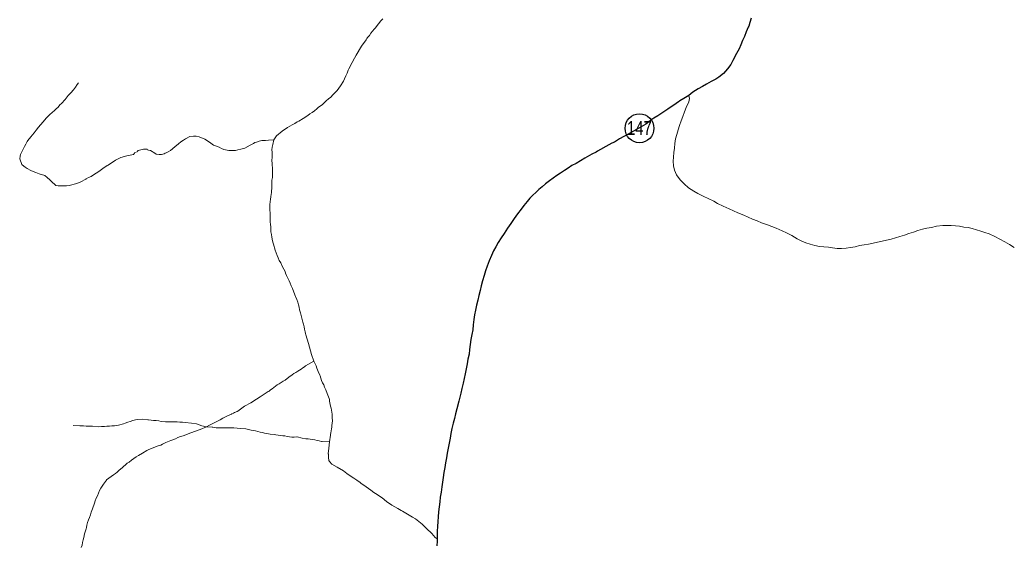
# Model space of a CAD drawing. Extents: x 781.9 to 808.1, y 7453.3 to 7481.5.
# Drawn here: x 790.69 to 796.4, y 7473.15 to 7476.16 of the extents above; entities that cross this region are included whole.
import ezdxf
from ezdxf.enums import TextEntityAlignment as Align

# ---------------------------------------------------------------- set-up
doc = ezdxf.new("R2010")
doc.units = 0
doc.header["$LTSCALE"] = 0.032
doc.linetypes.add('LONG_DASHED', pattern=[7.5, 6, -1.5])
doc.linetypes.add('MEDIUM_DASHED', pattern=[4.5, 3, -1.5])
for name, color, linetype, lineweight in [('13', 7, 'Continuous', 25), ('4', 7, 'LONG_DASHED', 25), ('5', 7, 'LONG_DASHED', 13), ('6', 7, 'MEDIUM_DASHED', 13)]:
    doc.layers.add(name, color=color, linetype=linetype, lineweight=lineweight)
doc.layers.add('61', color=7, linetype='Continuous')

msp = doc.modelspace()

# ---------------------------------------------------------------- linework, layer by layer
at = {"layer": '13'}
msp.add_circle((794.2522, 7475.5387), 0.083, dxfattribs=at)
msp.add_circle((794.2522, 7475.5387), 0.083, dxfattribs=at)
msp.add_circle((794.2522, 7475.5387), 0.083, dxfattribs=at)
at = {"layer": '4'}
for points in [[(794.8957, 7476.1726), (794.8876, 7476.1483), (794.8819, 7476.1264), (794.8778, 7476.1207), (794.8666, 7476.0932), (794.8568, 7476.0672), (794.8454, 7476.0429), (794.8349, 7476.0186), (794.826, 7475.9967), (794.8114, 7475.9691), (794.7902, 7475.9294), (794.7773, 7475.9051), (794.7586, 7475.8799), (794.7351, 7475.854), (794.7084, 7475.8329), (794.6906, 7475.8215), (794.6646, 7475.8069), (794.6387, 7475.7931), (794.6144, 7475.7786), (794.59, 7475.7656), (794.5588, 7475.7456), (794.5364, 7475.7272)], [(794.5364, 7475.7272), (794.5076, 7475.7104), (794.4852, 7475.696), (794.483, 7475.6942), (794.4765, 7475.6902), (794.4635, 7475.6805), (794.4149, 7475.648), (794.3582, 7475.6107), (794.3338, 7475.5961), (794.3233, 7475.5897), (794.2889, 7475.5625), (794.2481, 7475.5385), (794.1873, 7475.5057), (794.1377, 7475.4777), (794.1073, 7475.4585), (794.0922, 7475.4526), (794.076, 7475.4437), (794.0111, 7475.4064), (794.0022, 7475.4016), (793.9787, 7475.3902), (793.9382, 7475.3659), (793.9122, 7475.3504), (793.8879, 7475.3367), (793.8636, 7475.3237), (793.8417, 7475.3091), (793.8198, 7475.2953), (793.7979, 7475.2807), (793.7768, 7475.2669), (793.7549, 7475.2516), (793.7338, 7475.2353), (793.7119, 7475.2183), (793.6917, 7475.2021), (793.6722, 7475.1867), (793.656, 7475.1697), (793.6374, 7475.1542), (793.6203, 7475.1364), (793.6049, 7475.1178), (793.5863, 7475.0943), (793.5701, 7475.0732), (793.5506, 7475.0456), (793.5312, 7475.0197), (793.5117, 7474.9905), (793.4914, 7474.9629), (793.4728, 7474.9338), (793.4557, 7474.9078), (793.4395, 7474.8819), (793.4251, 7474.8563), (793.4123, 7474.8339), (793.4003, 7474.8059), (793.3868, 7474.7749), (793.3755, 7474.7457), (793.3666, 7474.7181), (793.3585, 7474.6905), (793.3479, 7474.6613), (793.3406, 7474.6322), (793.3342, 7474.6046), (793.3277, 7474.577)], [(793.3277, 7474.577), (793.3212, 7474.5495), (793.3139, 7474.5203), (793.3074, 7474.4927), (793.3025, 7474.4652), (793.2993, 7474.4376), (793.2944, 7474.4084)], [(793.2944, 7474.4084), (793.292, 7474.3792), (793.2871, 7474.3516), (793.2822, 7474.3241), (793.2774, 7474.2949), (793.2741, 7474.2657), (793.2709, 7474.2381), (793.2644, 7474.2106), (793.2595, 7474.183), (793.2539, 7474.1538), (793.249, 7474.1262), (793.2433, 7474.0987), (793.2368, 7474.0711), (793.2295, 7474.0419), (793.2231, 7474.0144), (793.2198, 7473.9989), (793.2125, 7473.969), (793.2012, 7473.9236), (793.1931, 7473.896), (793.1866, 7473.8684), (793.1801, 7473.8409), (793.1728, 7473.8117), (793.1663, 7473.7825), (793.1614, 7473.7549), (793.1566, 7473.7273), (793.1501, 7473.6982), (793.1444, 7473.669), (793.1404, 7473.6414), (793.1355, 7473.6138), (793.1314, 7473.5863), (793.1266, 7473.5571), (793.1217, 7473.5295), (793.1185, 7473.502), (793.1136, 7473.4744), (793.1096, 7473.4452), (793.1047, 7473.416), (793.1023, 7473.3884), (793.099, 7473.3609), (793.0958, 7473.3317), (793.0933, 7473.3025), (793.0909, 7473.2749), (793.0893, 7473.2474), (793.0877, 7473.2198), (793.0878, 7473.1767)], [(793.0878, 7473.1767), (793.0877, 7473.1631), (793.0861, 7473.1355)]]:
    msp.add_lwpolyline(points, dxfattribs=at)
at = {"layer": '5'}
msp.add_lwpolyline([(794.5364, 7475.7272), (794.5404, 7475.7106), (794.5364, 7475.6906), (794.5203, 7475.6586), (794.5106, 7475.6326), (794.5008, 7475.6067), (794.4927, 7475.5808), (794.4822, 7475.5548), (794.4741, 7475.5289), (794.4668, 7475.5029), (794.4603, 7475.477), (794.4562, 7475.451), (794.453, 7475.4251), (794.4505, 7475.3991), (794.4473, 7475.3732), (794.4465, 7475.3489), (794.4481, 7475.3229), (794.4538, 7475.297), (794.4643, 7475.271), (794.487, 7475.2427), (794.5089, 7475.2183), (794.5341, 7475.1956), (794.5649, 7475.177), (794.5884, 7475.164), (794.6224, 7475.1462), (794.6468, 7475.134), (794.6792, 7475.1194), (794.7019, 7475.1064), (794.7343, 7475.091), (794.7676, 7475.0748), (794.7927, 7475.0635), (794.8187, 7475.0529), (794.8519, 7475.0383), (794.877, 7475.0262), (794.903, 7475.0156), (794.9289, 7475.0059), (794.9549, 7474.9954), (794.9889, 7474.9824), (795.0132, 7474.9727), (795.0392, 7474.9637), (795.0732, 7474.9491), (795.0976, 7474.9378), (795.1291, 7474.9208), (795.1592, 7474.9021), (795.1835, 7474.89), (795.2095, 7474.8802), (795.2354, 7474.8721), (795.2613, 7474.8648), (795.2873, 7474.8583), (795.3132, 7474.8567), (795.3392, 7474.8543), (795.3635, 7474.8502), (795.3894, 7474.847), (795.4154, 7474.8462), (795.4413, 7474.8478), (795.4673, 7474.8527), (795.4932, 7474.8567), (795.5192, 7474.8632), (795.5451, 7474.8681), (795.5711, 7474.8713), (795.597, 7474.8778), (795.6229, 7474.8835), (795.6489, 7474.8892), (795.6748, 7474.8956), (795.7008, 7474.9013), (795.7251, 7474.9078), (795.751, 7474.9151), (795.777, 7474.9232), (795.8029, 7474.9329), (795.8289, 7474.9402), (795.8548, 7474.9499), (795.8808, 7474.9589), (795.9067, 7474.9629), (795.9327, 7474.9686), (795.9615, 7474.976), (795.9983, 7474.9792), (796.0218, 7474.9792), (796.0462, 7474.9783), (796.0705, 7474.9775), (796.0948, 7474.9751), (796.1191, 7474.9702), (796.1435, 7474.967), (796.1678, 7474.9613), (796.1921, 7474.9548), (796.2164, 7474.9475), (796.2407, 7474.9394), (796.2651, 7474.9313), (796.2967, 7474.9167), (796.3258, 7474.9005), (796.3551, 7474.8851), (796.3826, 7474.8689), (796.4093, 7474.8519)], dxfattribs=at)
at = {"layer": '6'}
for points in [[(792.7739, 7476.1693), (792.7625, 7476.1564), (792.7504, 7476.1402), (792.7301, 7476.115), (792.7244, 7476.1085), (792.7155, 7476.0972), (792.7066, 7476.0858), (792.6977, 7476.0721), (792.6871, 7476.0607), (792.6855, 7476.0591), (792.6839, 7476.055), (792.6806, 7476.0534), (792.6793, 7476.0476), (792.6524, 7476.0111), (792.6215, 7475.9586), (792.6125, 7475.9424), (792.5979, 7475.918), (792.5793, 7475.8815), (792.5761, 7475.8726), (792.5687, 7475.8564), (792.5615, 7475.8402), (792.5534, 7475.824), (792.5485, 7475.8094), (792.5307, 7475.7834), (792.512, 7475.7567), (792.5015, 7475.746), (792.4861, 7475.7307), (792.4747, 7475.7185), (792.4626, 7475.708), (792.4488, 7475.6966), (792.4269, 7475.6764), (792.4034, 7475.6578), (792.3945, 7475.6504), (792.3815, 7475.6399), (792.3685, 7475.6302), (792.3555, 7475.6212), (792.3426, 7475.6131), (792.3166, 7475.5953), (792.2915, 7475.5799), (792.2826, 7475.5751), (792.268, 7475.5661), (792.2534, 7475.558), (792.2396, 7475.5507), (792.2258, 7475.5426), (792.1949, 7475.5219)], [(790.6967, 7475.404), (790.7048, 7475.4186), (790.7129, 7475.4332), (790.7194, 7475.4478), (790.7283, 7475.4624), (790.7308, 7475.468), (790.7494, 7475.4899), (790.7673, 7475.5118), (790.7802, 7475.528), (790.7924, 7475.5451), (790.8045, 7475.5589), (790.8192, 7475.5751), (790.8378, 7475.5969), (790.8564, 7475.6164), (790.8726, 7475.631), (790.8832, 7475.6399), (790.8953, 7475.6496), (790.9059, 7475.661), (790.9164, 7475.6732), (790.9246, 7475.6821), (790.9456, 7475.7048), (790.9634, 7475.7267), (790.9788, 7475.742), (790.9943, 7475.7591), (791.0064, 7475.7753), (791.0161, 7475.7899), (791.0235, 7475.8005)], [(792.1467, 7475.4722), (792.1174, 7475.4701), (792.0985, 7475.4689), (792.0945, 7475.4688), (792.0783, 7475.468), (792.0621, 7475.464), (792.0475, 7475.4583), (792.0377, 7475.4559), (792.0312, 7475.4502), (792.0296, 7475.4504), (792.0103, 7475.4415), (791.9802, 7475.4251), (791.9729, 7475.4226), (791.9567, 7475.4177), (791.9405, 7475.4137), (791.9259, 7475.4113), (791.9113, 7475.4105), (791.8886, 7475.4104), (791.8602, 7475.4162), (791.8464, 7475.4218), (791.8318, 7475.4291), (791.8172, 7475.4348), (791.801, 7475.4421), (791.7775, 7475.4583), (791.7499, 7475.4762), (791.7459, 7475.4778), (791.7313, 7475.4834), (791.7167, 7475.4891), (791.7005, 7475.4923), (791.6859, 7475.4932), (791.6632, 7475.4907), (791.638, 7475.4778), (791.6267, 7475.4704), (791.6129, 7475.4599), (791.5991, 7475.4494), (791.5772, 7475.4315), (791.5521, 7475.4105), (791.5399, 7475.404), (791.5277, 7475.3983), (791.5221, 7475.3959), (791.5156, 7475.391), (791.501, 7475.3886), (791.4864, 7475.3886), (791.471, 7475.3902), (791.4621, 7475.3959), (791.437, 7475.4105), (791.4264, 7475.4129), (791.4199, 7475.4145), (791.4183, 7475.4177), (791.4118, 7475.4186), (791.3972, 7475.4194), (791.381, 7475.4153), (791.3656, 7475.4105), (791.3631, 7475.4072), (791.3607, 7475.404), (791.3478, 7475.3991), (791.3454, 7475.3959), (791.3389, 7475.387), (791.3008, 7475.381), (791.2675, 7475.3707), (791.2513, 7475.3634), (791.2367, 7475.3553), (791.2221, 7475.3448), (791.2075, 7475.3351), (791.1929, 7475.3269), (791.1881, 7475.3237), (791.1629, 7475.3067), (791.1402, 7475.2905), (791.1248, 7475.2807), (791.1102, 7475.271), (791.0956, 7475.2621), (791.081, 7475.2548), (791.0665, 7475.2475), (791.0656, 7475.2467), (791.0364, 7475.2313), (791.0129, 7475.2216), (790.9983, 7475.2175), (790.9838, 7475.2126), (790.9692, 7475.2086), (790.9546, 7475.2078), (790.94, 7475.2078), (790.9343, 7475.2078), (790.9059, 7475.2078), (790.8921, 7475.2102), (790.8864, 7475.2159), (790.8718, 7475.2288), (790.8572, 7475.2418), (790.8418, 7475.2556), (790.8289, 7475.267), (790.7957, 7475.2767), (790.777, 7475.2848), (790.7616, 7475.2896), (790.7478, 7475.2961), (790.7276, 7475.3075), (790.7154, 7475.3156)], [(792.1949, 7475.5219), (792.1636, 7475.4946), (792.1467, 7475.4722)], [(792.1467, 7475.4722), (792.1407, 7475.4445), (792.1382, 7475.43), (792.1366, 7475.4154), (792.1374, 7475.4008)], [(790.7154, 7475.3156), (790.6991, 7475.3278), (790.6959, 7475.3302), (790.6854, 7475.3635), (790.687, 7475.3788), (790.6894, 7475.3878), (790.6967, 7475.404)], [(792.1374, 7475.4008), (792.1374, 7475.3781), (792.1367, 7475.3481), (792.1374, 7475.3408), (792.1374, 7475.3262), (792.139, 7475.3116), (792.139, 7475.297), (792.139, 7475.284), (792.139, 7475.2694), (792.139, 7475.2548), (792.1366, 7475.2402), (792.1358, 7475.2256), (792.135, 7475.2029), (792.1334, 7475.1681), (792.1318, 7475.1592), (792.1301, 7475.1446), (792.1277, 7475.13), (792.1261, 7475.1154), (792.1245, 7475.1008), (792.1245, 7475.0862), (792.1245, 7475.0716), (792.1261, 7475.0489), (792.1253, 7475.0189), (792.1253, 7475.0148), (792.1269, 7475.0002), (792.1277, 7474.9857), (792.1293, 7474.9711), (792.1309, 7474.9565), (792.1309, 7474.9419), (792.1334, 7474.9273), (792.1366, 7474.9127), (792.1399, 7474.8916), (792.1488, 7474.8584), (792.1512, 7474.8511), (792.1553, 7474.8365), (792.1609, 7474.8219), (792.1658, 7474.8073), (792.1731, 7474.7927), (792.1788, 7474.7781), (792.1877, 7474.7635), (792.1974, 7474.7408), (792.212, 7474.714), (792.2153, 7474.7051), (792.2209, 7474.6905), (792.2283, 7474.6759), (792.2364, 7474.6613), (792.242, 7474.6468), (792.2469, 7474.6322), (792.2542, 7474.6159), (792.2623, 7474.5965), (792.272, 7474.5713), (792.2736, 7474.5673), (792.2793, 7474.5527), (792.285, 7474.5381), (792.289, 7474.5235), (792.2923, 7474.5089), (792.2955, 7474.4943), (792.3004, 7474.4757), (792.3069, 7474.4538), (792.315, 7474.4238), (792.3174, 7474.4116), (792.3215, 7474.397), (792.3247, 7474.3824), (792.328, 7474.3679), (792.3304, 7474.3581), (792.3314, 7474.3509), (792.347, 7474.2992), (792.3651, 7474.2362), (792.378, 7474.1977)], [(792.378, 7474.1977), (792.3597, 7474.1888), (792.3304, 7474.1724), (792.3239, 7474.1667), (792.3142, 7474.1594), (792.3053, 7474.153), (792.2955, 7474.1473), (792.285, 7474.1408), (792.2745, 7474.1335), (792.2631, 7474.127), (792.2526, 7474.1197), (792.2339, 7474.1067), (792.212, 7474.0889), (792.2096, 7474.0873), (792.2007, 7474.0832), (792.1902, 7474.0759), (792.1788, 7474.0687), (792.1675, 7474.0614), (792.1569, 7474.0549), (792.1472, 7474.0468), (792.1374, 7474.0394), (792.1285, 7474.033), (792.1204, 7474.0265), (792.1156, 7474.0242), (792.0678, 7473.9941), (792.0485, 7473.9789), (792.0152, 7473.9584), (791.9783, 7473.9392), (791.9482, 7473.9163), (791.9461, 7473.9146), (791.9356, 7473.9097), (791.921, 7473.9033), (791.9145, 7473.9), (791.9048, 7473.8952), (791.9031, 7473.8943), (791.8991, 7473.8919), (791.8853, 7473.8854), (791.8691, 7473.8773), (791.8529, 7473.87), (791.8383, 7473.8611), (791.831, 7473.8571), (791.8073, 7473.8447), (791.7776, 7473.8294), (791.7596, 7473.8214)], [(792.378, 7474.1977), (792.3912, 7474.1716), (792.3952, 7474.1587), (792.4018, 7474.1392), (792.4123, 7474.1173), (792.4139, 7474.1133), (792.4179, 7474.1003), (792.422, 7474.0873), (792.4277, 7474.0744), (792.4342, 7474.0614), (792.4398, 7474.0484), (792.4415, 7474.0451), (792.4439, 7474.0379), (792.446, 7474.0344), (792.455, 7474.012), (792.4666, 7473.9843), (792.4674, 7473.9787), (792.4682, 7473.969), (792.469, 7473.9592), (792.4723, 7473.9495), (792.4739, 7473.9398), (792.4771, 7473.9284), (792.4788, 7473.9171), (792.482, 7473.9057), (792.4828, 7473.8944), (792.4828, 7473.883), (792.4836, 7473.8717)], [(791.7596, 7473.8214), (791.7331, 7473.8273), (791.7014, 7473.8373), (791.6733, 7473.8421), (791.6376, 7473.8457), (791.621, 7473.8465), (791.6064, 7473.8473), (791.5918, 7473.8489), (791.5772, 7473.8497), (791.5626, 7473.8489), (791.5521, 7473.849), (791.5237, 7473.8489), (791.4994, 7473.8522), (791.4848, 7473.8546), (791.4702, 7473.8562), (791.4556, 7473.857), (791.441, 7473.8587), (791.4264, 7473.8603), (791.4224, 7473.8603), (791.3891, 7473.8652), (791.3648, 7473.8635), (791.3502, 7473.8603), (791.3356, 7473.857), (791.321, 7473.8505), (791.3064, 7473.8473), (791.2918, 7473.8408), (791.2829, 7473.8377), (791.2529, 7473.8311), (791.2302, 7473.827), (791.2156, 7473.8254), (791.201, 7473.8238), (791.1864, 7473.8238), (791.1719, 7473.8222), (791.1556, 7473.8222), (791.137, 7473.8214), (791.1037, 7473.8238), (791.081, 7473.8238), (791.0665, 7473.8238), (791.0519, 7473.8254), (791.0356, 7473.8262), (791.0299, 7473.8259), (790.9918, 7473.8287)], [(792.4836, 7473.8717), (792.4844, 7473.8554), (792.482, 7473.8287), (792.4804, 7473.8182), (792.4796, 7473.8084), (792.4771, 7473.7971), (792.4747, 7473.7857)], [(791.7596, 7473.8214), (791.7242, 7473.8057), (791.6692, 7473.7852), (791.6263, 7473.7696), (791.617, 7473.7671), (791.6097, 7473.7646), (791.5951, 7473.7597), (791.5805, 7473.7516), (791.5659, 7473.746), (791.5537, 7473.7411), (791.5253, 7473.7298), (791.5066, 7473.7208), (791.4962, 7473.716), (791.4816, 7473.7119), (791.467, 7473.7062), (791.4524, 7473.6997), (791.4378, 7473.6949), (791.4232, 7473.6876), (791.4159, 7473.6852), (791.3908, 7473.6698), (791.3689, 7473.6551), (791.3551, 7473.6487), (791.3413, 7473.6381), (791.3275, 7473.6284), (791.3153, 7473.6178), (791.3032, 7473.6114), (791.2991, 7473.6082), (791.2756, 7473.587), (791.2544, 7473.5692), (791.2448, 7473.5603), (791.2352, 7473.5522), (791.2237, 7473.5441), (791.2108, 7473.5352), (791.1978, 7473.5246), (791.1848, 7473.5149), (791.184, 7473.5141), (791.1678, 7473.4914), (791.1524, 7473.4679), (791.1442, 7473.4533), (791.1378, 7473.4387), (791.1321, 7473.4241), (791.1256, 7473.4095), (791.1199, 7473.3949), (791.1143, 7473.3811), (791.1029, 7473.3479), (791.0964, 7473.3292), (791.0915, 7473.3139), (791.0859, 7473.2994), (791.081, 7473.2847), (791.0753, 7473.2701), (791.0713, 7473.2555), (791.0688, 7473.2409), (791.0665, 7473.2336)], [(792.4669, 7473.7339), (792.4261, 7473.7355), (792.422, 7473.7362), (792.4091, 7473.7395), (792.3961, 7473.7419), (792.3831, 7473.7459), (792.3702, 7473.7476), (792.3572, 7473.7492), (792.3442, 7473.7508), (792.3312, 7473.7516), (792.3102, 7473.7556), (792.2818, 7473.763), (792.2794, 7473.7622), (792.2648, 7473.7605), (792.2502, 7473.7614), (792.2372, 7473.763), (792.2242, 7473.7654), (792.2112, 7473.7679), (792.1983, 7473.7695), (792.1853, 7473.7703), (792.1723, 7473.7727), (792.1594, 7473.7752), (792.1537, 7473.776), (792.1269, 7473.7792), (792.1075, 7473.7824), (792.0945, 7473.7841), (792.0815, 7473.7873), (792.0686, 7473.7906), (792.0556, 7473.793), (792.0426, 7473.7979), (792.0296, 7473.8003), (792.0167, 7473.8011), (791.9858, 7473.8087), (791.9553, 7473.8111), (791.9172, 7473.8139), (791.9032, 7473.8149), (791.8902, 7473.8149), (791.8772, 7473.8157), (791.8642, 7473.8157), (791.8496, 7473.8149), (791.8407, 7473.8149), (791.8156, 7473.8157), (791.7961, 7473.8181), (791.7921, 7473.8189), (791.762, 7473.8209), (791.7596, 7473.8214)], [(792.4747, 7473.7857), (792.4739, 7473.7768), (792.4742, 7473.7732), (792.4669, 7473.7339)], [(792.4669, 7473.7339), (792.4634, 7473.6982), (792.461, 7473.6649), (792.4617, 7473.6625), (792.4617, 7473.6446), (792.4642, 7473.6276), (792.4674, 7473.6211), (792.482, 7473.6065), (792.5112, 7473.5879), (792.5477, 7473.5668), (792.5672, 7473.553), (792.5866, 7473.5384), (792.6069, 7473.5254), (792.6247, 7473.5133), (792.6442, 7473.5003), (792.6482, 7473.4971), (792.6782, 7473.476), (792.7058, 7473.4557), (792.7237, 7473.4436), (792.7415, 7473.4314), (792.7609, 7473.4184), (792.7707, 7473.412), (792.7966, 7473.3917), (792.8258, 7473.3706), (792.8436, 7473.3608), (792.8615, 7473.3503), (792.8809, 7473.339), (792.8882, 7473.3349), (792.9166, 7473.3187), (792.9458, 7473.3017), (792.9636, 7473.2903), (792.9815, 7473.2749), (793.0009, 7473.2603), (793.005, 7473.2563), (793.0268, 7473.2352), (793.0569, 7473.2067), (793.0765, 7473.1839), (793.0878, 7473.1767)], [(791.0665, 7473.2336), (791.0583, 7473.2052), (791.0534, 7473.1841), (791.0494, 7473.1695), (791.0461, 7473.1549), (791.0437, 7473.1404), (791.0388, 7473.1258)]]:
    msp.add_lwpolyline(points, dxfattribs=at)

# ---------------------------------------------------------------- texts
at = {"layer": '61', "width": 0.8}
msp.add_text('147', height=0.08, dxfattribs=at).set_placement((794.2514, 7475.5004), align=Align.CENTER)

doc.saveas('drawing.dxf')
